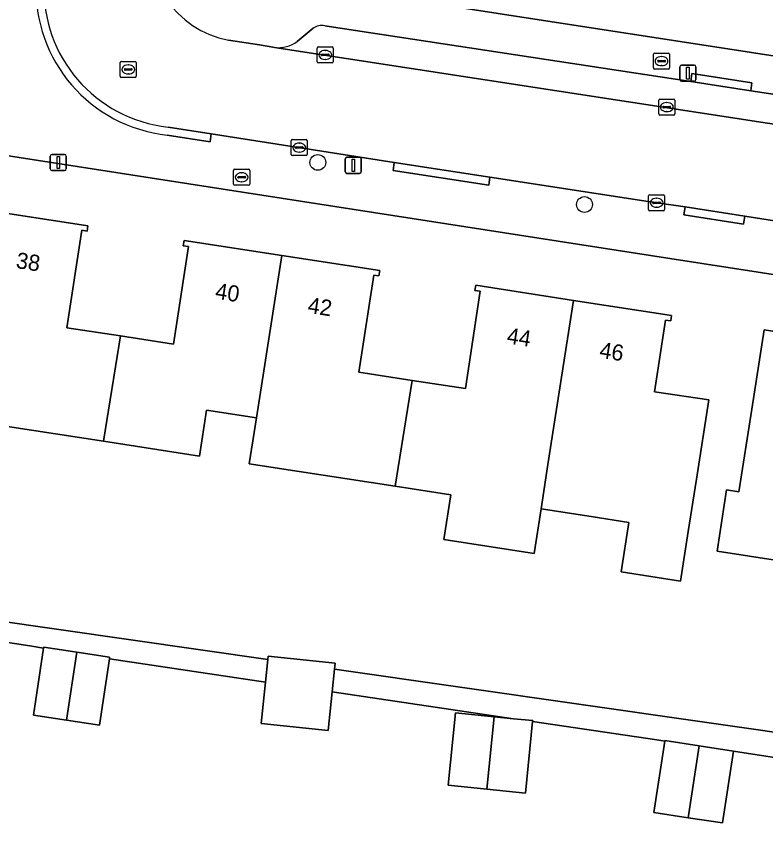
# Model space of a CAD drawing. Extents: x 161483 to 162250, y 379484 to 380833.
# Drawn here: x 161783.2 to 161829.9, y 380603.9 to 380654.4 of the extents above; entities that cross this region are included whole.
import ezdxf

# ---------------------------------------------------------------- set-up
doc = ezdxf.new("R2010")
doc.units = 0
for name, color, linetype in [('IMGEO_Boom', 7, 'Continuous'), ('IMGEO_Brandkraan', 7, 'Continuous'), ('IMGEO_Erf', 7, 'Continuous'), ('IMGEO_Kolk', 7, 'Continuous'), ('IMGEO_Lichtmast', 7, 'Continuous'), ('IMGEO_Pand', 7, 'Continuous'), ('IMGEO_Pand_nummerreeks', 7, 'Continuous'), ('IMGEO_Parkeervlak_open', 7, 'Continuous'), ('IMGEO_Rijbaan_lokaal_open', 7, 'Continuous'), ('IMGEO_Rioolput', 7, 'Continuous'), ('IMGEO_Voetpad_open', 7, 'Continuous')]:
    doc.layers.add(name, color=color, linetype=linetype)

msp = doc.modelspace()

# ---------------------------------------------------------------- linework, layer by layer
at = {"layer": 'IMGEO_Boom'}
for centre in [(161801.982, 380645.267), (161818.588, 380642.647)]:
    msp.add_circle(centre, 0.489, dxfattribs=at)
at = {"layer": 'IMGEO_Brandkraan'}
for p, q in [((161822.886, 380651.149), (161822.886, 380652.001)), ((161822.961, 380652.075), (161823.813, 380652.075)), ((161823.887, 380652.001), (161823.887, 380651.149)), ((161823.145, 380651.569), (161823.145, 380651.581)), ((161823.583, 380651.532), (161823.185, 380651.532)), ((161823.188, 380651.618), (161823.586, 380651.618)), ((161823.374, 380651.855), (161823.399, 380651.855)), ((161823.629, 380651.581), (161823.629, 380651.569)), ((161823.813, 380651.075), (161822.961, 380651.075)), ((161823.397, 380651.295), (161823.372, 380651.295)), ((161796.739, 380643.916), (161796.739, 380644.768)), ((161796.814, 380644.842), (161797.666, 380644.842)), ((161797.227, 380644.622), (161797.252, 380644.622)), ((161797.74, 380644.768), (161797.74, 380643.916)), ((161796.998, 380644.336), (161796.998, 380644.348)), ((161797.436, 380644.299), (161797.038, 380644.299)), ((161797.041, 380644.385), (161797.439, 380644.385)), ((161797.25, 380644.062), (161797.225, 380644.062)), ((161797.482, 380644.348), (161797.482, 380644.336)), ((161797.666, 380643.842), (161796.814, 380643.842))]:
    msp.add_line(p, q, dxfattribs=at)
for points in [[(161822.886, 380651.149), (161822.886, 380652.001)], [(161822.961, 380652.075), (161823.813, 380652.075)], [(161823.887, 380652.001), (161823.887, 380651.149)], [(161823.813, 380651.075), (161822.961, 380651.075)], [(161796.739, 380643.916), (161796.739, 380644.768)], [(161796.814, 380644.842), (161797.666, 380644.842)], [(161797.74, 380644.768), (161797.74, 380643.916)], [(161797.666, 380643.842), (161796.814, 380643.842)]]:
    msp.add_lwpolyline(points, dxfattribs=at)
for centre, radius, start, end in [((161822.963, 380651.999), 0.0765, 91.552, 178.448), ((161822.963, 380651.999), 0.0765, 91.552, 178.448), ((161823.811, 380651.999), 0.0765, 1.552, 88.448), ((161823.811, 380651.999), 0.0765, 1.552, 88.448), ((161823.185, 380651.578), 0.0403, 85.8775, 175.7526), ((161823.182, 380651.568), 0.0366, 178.938, 274.7102), ((161823.586, 380651.575), 0.043, 264.8664, 352.4533), ((161823.59, 380651.58), 0.0386, 1.7309, 96.639), ((161822.963, 380651.151), 0.0765, 181.552, 268.448), ((161822.963, 380651.151), 0.0765, 181.552, 268.448), ((161823.811, 380651.151), 0.0765, 271.552, 358.448), ((161823.811, 380651.151), 0.0765, 271.552, 358.448), ((161796.816, 380644.766), 0.0765, 91.552, 178.448), ((161796.816, 380644.766), 0.0765, 91.552, 178.448), ((161797.664, 380644.766), 0.0765, 1.552, 88.448), ((161797.664, 380644.766), 0.0765, 1.552, 88.448), ((161796.816, 380643.918), 0.0765, 181.552, 268.448), ((161796.816, 380643.918), 0.0765, 181.552, 268.448), ((161797.038, 380644.345), 0.0403, 85.8775, 175.7526), ((161797.035, 380644.335), 0.0366, 178.938, 274.7102), ((161797.439, 380644.342), 0.043, 264.8664, 352.4533), ((161797.443, 380644.347), 0.0386, 1.7309, 96.639), ((161797.664, 380643.918), 0.0765, 271.552, 358.448), ((161797.664, 380643.918), 0.0765, 271.552, 358.448)]:
    msp.add_arc(centre, radius, start, end, dxfattribs=at)
for centre, major_axis, ratio, start_param, end_param in [((161823.373, 380651.575), (-0.387, 0.002), 0.722429, 4.712389, 7.853982), ((161823.398, 380651.575), (-0.39, 0.002), 0.717154, 1.570796, 4.712389), ((161797.226, 380644.342), (-0.387, 0.002), 0.722429, 4.712389, 7.853982), ((161797.251, 380644.342), (-0.39, 0.002), 0.717154, 1.570796, 4.712389)]:
    msp.add_ellipse(centre, major_axis=major_axis, ratio=ratio, start_param=start_param, end_param=end_param, dxfattribs=at)
at = {"layer": 'IMGEO_Erf'}
for points in [[(161797.167, 380657.035), (161908.673, 380639.841), (161916.207, 380638.698), (161924.835, 380637.387), (161925.546, 380637.356)], [(161925.898, 380623.516), (161823.912, 380639.282), (161780.025, 380646.103), (161736.717, 380652.782), (161731.74, 380653.484)], [(161781.58, 380642.258), (161787.666, 380641.32), (161787.616, 380640.993), (161787.29, 380641.044), (161786.358, 380634.978), (161789.687, 380634.467), (161792.998, 380633.958), (161793.93, 380640.023), (161793.604, 380640.074), (161793.654, 380640.4), (161799.746, 380639.465), (161805.836, 380638.53), (161805.786, 380638.203), (161805.46, 380638.254), (161804.538, 380632.197), (161807.856, 380631.692), (161811.168, 380631.187), (161812.09, 380637.243), (161811.764, 380637.294), (161811.814, 380637.62), (161817.913, 380636.675), (161824.006, 380635.73), (161823.956, 380635.403), (161823.63, 380635.454), (161822.953, 380630.988), (161826.326, 380630.476), (161825.556, 380625.536), (161825.049, 380622.281), (161824.568, 380619.197), (161820.88, 380619.771), (161821.359, 380622.85), (161818.996, 380623.215), (161815.883, 380623.695), (161815.451, 380620.921), (161809.836, 380621.788), (161810.265, 380624.564), (161806.802, 380625.099), (161800.829, 380626.022), (161797.717, 380626.503), (161798.158, 380629.356), (161795.049, 380629.836), (161794.609, 380626.983), (161788.635, 380627.906), (161782.662, 380628.828)], [(161750.43, 380622.432), (161754.893, 380621.765), (161759.356, 380621.098), (161763.819, 380620.431), (161768.779, 380619.69), (161768.624, 380618.651), (161798.865, 380614.315), (161798.885, 380614.516), (161803.054, 380614.092), (161803.016, 380613.72), (161879.814, 380602.708)], [(161832.16, 380607.936), (161827.864, 380608.608), (161827.178, 380604.134), (161825.044, 380604.461), (161822.91, 380604.788), (161823.592, 380609.237), (161823.099, 380609.308), (161815.359, 380610.453), (161814.905, 380605.994), (161812.5, 380606.239), (161810.095, 380606.484), (161810.554, 380610.997), (161812.959, 380610.752), (161814.172, 380610.628), (161802.871, 380612.3), (161802.627, 380609.9), (161798.458, 380610.324), (161798.722, 380612.913), (161789, 380614.351), (161788.386, 380610.234), (161786.334, 380610.54), (161784.283, 380610.847), (161784.905, 380615.016), (161784.042, 380615.157), (161777.083, 380616.222)]]:
    msp.add_lwpolyline(points, dxfattribs=at)
msp.add_lwpolyline([(161830.564, 380618.414), (161830.878, 380620.439), (161826.847, 380621.064), (161827.438, 380624.873), (161828.206, 380624.754), (161829.004, 380629.9), (161829.77, 380634.84), (161835.7, 380633.93), (161835.178, 380630.68), (161838.733, 380630.109), (161837.972, 380625.168), (161836.784, 380617.449)], close=True, dxfattribs=at)
at = {"layer": 'IMGEO_Kolk'}
for p, q in [((161801.946, 380651.539), (161801.946, 380652.391)), ((161802.021, 380652.465), (161802.873, 380652.465)), ((161802.248, 380652.008), (161802.646, 380652.008)), ((161802.434, 380652.245), (161802.459, 380652.245)), ((161802.947, 380652.391), (161802.947, 380651.539)), ((161802.205, 380651.959), (161802.205, 380651.971)), ((161802.643, 380651.922), (161802.245, 380651.922)), ((161802.457, 380651.685), (161802.432, 380651.685)), ((161802.689, 380651.971), (161802.689, 380651.959)), ((161802.873, 380651.465), (161802.021, 380651.465)), ((161823.211, 380648.286), (161823.211, 380649.138)), ((161823.286, 380649.212), (161824.138, 380649.212)), ((161823.699, 380648.992), (161823.724, 380648.992)), ((161824.212, 380649.138), (161824.212, 380648.286)), ((161823.47, 380648.706), (161823.47, 380648.718)), ((161823.908, 380648.669), (161823.51, 380648.669)), ((161823.513, 380648.755), (161823.911, 380648.755)), ((161823.954, 380648.718), (161823.954, 380648.706)), ((161824.138, 380648.212), (161823.286, 380648.212)), ((161823.722, 380648.432), (161823.697, 380648.432)), ((161800.327, 380645.764), (161800.327, 380646.616)), ((161800.402, 380646.69), (161801.254, 380646.69)), ((161800.815, 380646.47), (161800.84, 380646.47)), ((161801.328, 380646.616), (161801.328, 380645.764)), ((161800.586, 380646.184), (161800.586, 380646.196)), ((161801.024, 380646.147), (161800.626, 380646.147)), ((161800.629, 380646.233), (161801.027, 380646.233)), ((161801.07, 380646.196), (161801.07, 380646.184)), ((161801.254, 380645.69), (161800.402, 380645.69)), ((161800.838, 380645.91), (161800.813, 380645.91)), ((161822.579, 380642.331), (161822.579, 380643.183)), ((161822.654, 380643.257), (161823.506, 380643.257)), ((161823.067, 380643.037), (161823.092, 380643.037)), ((161823.58, 380643.183), (161823.58, 380642.331)), ((161822.838, 380642.751), (161822.838, 380642.763)), ((161823.276, 380642.714), (161822.878, 380642.714)), ((161822.881, 380642.8), (161823.279, 380642.8)), ((161823.09, 380642.477), (161823.065, 380642.477)), ((161823.322, 380642.763), (161823.322, 380642.751)), ((161823.506, 380642.257), (161822.654, 380642.257))]:
    msp.add_line(p, q, dxfattribs=at)
for points in [[(161801.946, 380651.539), (161801.946, 380652.391)], [(161802.021, 380652.465), (161802.873, 380652.465)], [(161802.947, 380652.391), (161802.947, 380651.539)], [(161802.873, 380651.465), (161802.021, 380651.465)], [(161823.211, 380648.286), (161823.211, 380649.138)], [(161823.286, 380649.212), (161824.138, 380649.212)], [(161824.212, 380649.138), (161824.212, 380648.286)], [(161824.138, 380648.212), (161823.286, 380648.212)], [(161800.327, 380645.764), (161800.327, 380646.616)], [(161800.402, 380646.69), (161801.254, 380646.69)], [(161801.328, 380646.616), (161801.328, 380645.764)], [(161801.254, 380645.69), (161800.402, 380645.69)], [(161822.579, 380642.331), (161822.579, 380643.183)], [(161822.654, 380643.257), (161823.506, 380643.257)], [(161823.58, 380643.183), (161823.58, 380642.331)], [(161823.506, 380642.257), (161822.654, 380642.257)]]:
    msp.add_lwpolyline(points, dxfattribs=at)
for centre, radius, start, end in [((161802.023, 380652.389), 0.0765, 91.552, 178.448), ((161802.023, 380652.389), 0.0765, 91.552, 178.448), ((161802.245, 380651.968), 0.0403, 85.8775, 175.7526), ((161802.65, 380651.97), 0.0386, 1.7309, 96.639), ((161802.871, 380652.389), 0.0765, 1.552, 88.448), ((161802.871, 380652.389), 0.0765, 1.552, 88.448), ((161802.023, 380651.541), 0.0765, 181.552, 268.448), ((161802.023, 380651.541), 0.0765, 181.552, 268.448), ((161802.242, 380651.958), 0.0366, 178.938, 274.7102), ((161802.646, 380651.965), 0.043, 264.8664, 352.4533), ((161802.871, 380651.541), 0.0765, 271.552, 358.448), ((161802.871, 380651.541), 0.0765, 271.552, 358.448), ((161823.288, 380649.136), 0.0765, 91.552, 178.448), ((161823.288, 380649.136), 0.0765, 91.552, 178.448), ((161824.136, 380649.136), 0.0765, 1.552, 88.448), ((161824.136, 380649.136), 0.0765, 1.552, 88.448), ((161823.51, 380648.715), 0.0403, 85.8775, 175.7526), ((161823.507, 380648.705), 0.0366, 178.938, 274.7102), ((161823.911, 380648.712), 0.043, 264.8664, 352.4533), ((161823.915, 380648.717), 0.0386, 1.7309, 96.639), ((161823.288, 380648.288), 0.0765, 181.552, 268.448), ((161823.288, 380648.288), 0.0765, 181.552, 268.448), ((161824.136, 380648.288), 0.0765, 271.552, 358.448), ((161824.136, 380648.288), 0.0765, 271.552, 358.448), ((161800.404, 380646.614), 0.0765, 91.552, 178.448), ((161800.404, 380646.614), 0.0765, 91.552, 178.448), ((161801.252, 380646.614), 0.0765, 1.552, 88.448), ((161801.252, 380646.614), 0.0765, 1.552, 88.448), ((161800.626, 380646.193), 0.0403, 85.8775, 175.7526), ((161800.623, 380646.183), 0.0366, 178.938, 274.7102), ((161801.027, 380646.19), 0.043, 264.8664, 352.4533), ((161801.031, 380646.195), 0.0386, 1.7309, 96.639), ((161800.404, 380645.766), 0.0765, 181.552, 268.448), ((161800.404, 380645.766), 0.0765, 181.552, 268.448), ((161801.252, 380645.766), 0.0765, 271.552, 358.448), ((161801.252, 380645.766), 0.0765, 271.552, 358.448), ((161822.656, 380643.181), 0.0765, 91.552, 178.448), ((161822.656, 380643.181), 0.0765, 91.552, 178.448), ((161823.504, 380643.181), 0.0765, 1.552, 88.448), ((161823.504, 380643.181), 0.0765, 1.552, 88.448), ((161822.878, 380642.76), 0.0403, 85.8775, 175.7526), ((161822.875, 380642.75), 0.0366, 178.938, 274.7102), ((161823.279, 380642.757), 0.043, 264.8664, 352.4533), ((161823.283, 380642.762), 0.0386, 1.7309, 96.639), ((161822.656, 380642.333), 0.0765, 181.552, 268.448), ((161822.656, 380642.333), 0.0765, 181.552, 268.448), ((161823.504, 380642.333), 0.0765, 271.552, 358.448), ((161823.504, 380642.333), 0.0765, 271.552, 358.448)]:
    msp.add_arc(centre, radius, start, end, dxfattribs=at)
for centre, major_axis, ratio, start_param, end_param in [((161802.433, 380651.965), (-0.387, 0.002), 0.722429, 4.712389, 7.853982), ((161802.458, 380651.965), (-0.39, 0.002), 0.717154, 1.570796, 4.712389), ((161823.698, 380648.712), (-0.387, 0.002), 0.722429, 4.712389, 7.853982), ((161823.723, 380648.712), (-0.39, 0.002), 0.717154, 1.570796, 4.712389), ((161800.814, 380646.19), (-0.387, 0.002), 0.722429, 4.712389, 7.853982), ((161800.839, 380646.19), (-0.39, 0.002), 0.717154, 1.570796, 4.712389), ((161823.066, 380642.757), (-0.387, 0.002), 0.722429, 4.712389, 7.853982), ((161823.091, 380642.757), (-0.39, 0.002), 0.717154, 1.570796, 4.712389)]:
    msp.add_ellipse(centre, major_axis=major_axis, ratio=ratio, start_param=start_param, end_param=end_param, dxfattribs=at)
at = {"layer": 'IMGEO_Lichtmast'}
for p, q in [((161824.53, 380650.429), (161824.53, 380651.229)), ((161824.53, 380651.229), (161824.53, 380650.429)), ((161824.63, 380651.329), (161825.42, 380651.329)), ((161825.42, 380651.329), (161824.63, 380651.329)), ((161825.52, 380651.229), (161825.52, 380650.429)), ((161825.52, 380650.429), (161825.52, 380651.229)), ((161825.42, 380650.329), (161824.63, 380650.329)), ((161824.63, 380650.329), (161825.42, 380650.329)), ((161785.323, 380644.867), (161785.323, 380645.667)), ((161785.323, 380645.667), (161785.323, 380644.867)), ((161785.423, 380645.767), (161786.213, 380645.767)), ((161786.213, 380645.767), (161785.423, 380645.767)), ((161786.313, 380645.667), (161786.313, 380644.867)), ((161786.313, 380644.867), (161786.313, 380645.667)), ((161803.694, 380644.688), (161803.694, 380645.488)), ((161803.694, 380645.488), (161803.694, 380644.688)), ((161803.794, 380645.588), (161804.584, 380645.588)), ((161804.584, 380645.588), (161803.794, 380645.588)), ((161804.684, 380645.488), (161804.684, 380644.688)), ((161804.684, 380644.688), (161804.684, 380645.488)), ((161786.213, 380644.767), (161785.423, 380644.767)), ((161785.423, 380644.767), (161786.213, 380644.767)), ((161804.584, 380644.588), (161803.794, 380644.588)), ((161803.794, 380644.588), (161804.584, 380644.588))]:
    msp.add_line(p, q, dxfattribs=at)
for points in [[(161824.95, 380651.204), (161825.1, 380651.204), (161825.1, 380650.454), (161824.95, 380650.454), (161824.95, 380651.204)], [(161785.743, 380645.642), (161785.893, 380645.642), (161785.893, 380644.892), (161785.743, 380644.892), (161785.743, 380645.642)], [(161804.114, 380645.463), (161804.264, 380645.463), (161804.264, 380644.713), (161804.114, 380644.713), (161804.114, 380645.463)]]:
    msp.add_lwpolyline(points, dxfattribs=at)
for centre, start, end in [((161824.63, 380651.229), 90, 180), ((161824.63, 380651.229), 90, 180), ((161825.42, 380651.229), 0, 90), ((161825.42, 380651.229), 360, 90), ((161824.63, 380650.429), 180, 270), ((161824.63, 380650.429), 180, 270), ((161825.42, 380650.429), 270, 0), ((161825.42, 380650.429), 270, 0), ((161785.423, 380645.667), 90, 180), ((161785.423, 380645.667), 90, 180), ((161786.213, 380645.667), 0, 90), ((161786.213, 380645.667), 360, 90), ((161803.794, 380645.488), 90, 180), ((161803.794, 380645.488), 90, 180), ((161804.584, 380645.488), 0, 90), ((161804.584, 380645.488), 360, 90), ((161785.423, 380644.867), 180, 270), ((161785.423, 380644.867), 180, 270), ((161786.213, 380644.867), 270, 0), ((161786.213, 380644.867), 270, 0), ((161803.794, 380644.688), 180, 270), ((161803.794, 380644.688), 180, 270), ((161804.584, 380644.688), 270, 0), ((161804.584, 380644.688), 270, 0)]:
    msp.add_arc(centre, 0.1, start, end, dxfattribs=at)
at = {"layer": 'IMGEO_Pand'}
for points in [[(161781.58, 380642.258), (161779.99, 380632.163), (161779.541, 380629.311), (161779.401, 380628.422), (161782.525, 380627.941), (161782.662, 380628.828), (161788.635, 380627.906), (161789.687, 380634.467), (161786.358, 380634.978), (161787.29, 380641.044), (161787.616, 380640.993), (161787.666, 380641.32)], [(161789.687, 380634.467), (161788.635, 380627.906), (161794.609, 380626.983), (161795.049, 380629.836), (161798.158, 380629.356), (161799.746, 380639.465), (161793.654, 380640.4), (161793.604, 380640.074), (161793.93, 380640.023), (161792.998, 380633.958)], [(161799.746, 380639.465), (161798.158, 380629.356), (161797.717, 380626.503), (161800.829, 380626.022), (161806.802, 380625.099), (161807.856, 380631.692), (161804.538, 380632.197), (161805.46, 380638.254), (161805.786, 380638.203), (161805.836, 380638.53)], [(161817.913, 380636.675), (161811.814, 380637.62), (161811.764, 380637.294), (161812.09, 380637.243), (161811.168, 380631.187), (161807.856, 380631.692), (161806.802, 380625.099), (161810.265, 380624.564), (161809.836, 380621.788), (161815.451, 380620.921), (161815.883, 380623.695), (161816.314, 380626.46)], [(161817.913, 380636.675), (161816.314, 380626.46), (161815.883, 380623.695), (161818.996, 380623.215), (161821.359, 380622.85), (161820.88, 380619.771), (161824.568, 380619.197), (161825.049, 380622.281), (161825.556, 380625.536), (161826.326, 380630.476), (161822.953, 380630.988), (161823.63, 380635.454), (161823.956, 380635.403), (161824.006, 380635.73)], [(161830.878, 380620.439), (161830.564, 380618.414), (161836.784, 380617.449), (161837.972, 380625.168), (161838.733, 380630.109), (161835.178, 380630.68), (161835.7, 380633.93), (161829.77, 380634.84), (161829.004, 380629.9), (161828.206, 380624.754), (161827.438, 380624.873), (161826.847, 380621.064)], [(161786.965, 380614.771), (161784.914, 380615.077), (161784.905, 380615.016), (161784.283, 380610.847), (161786.334, 380610.54)], [(161789, 380614.351), (161789.017, 380614.464), (161786.965, 380614.771), (161786.334, 380610.54), (161788.386, 380610.234)], [(161803.016, 380613.72), (161803.054, 380614.092), (161798.885, 380614.516), (161798.865, 380614.315), (161798.722, 380612.913), (161798.458, 380610.324), (161802.627, 380609.9), (161802.871, 380612.3)], [(161812.959, 380610.752), (161810.554, 380610.997), (161810.095, 380606.484), (161812.5, 380606.239)], [(161815.359, 380610.453), (161815.364, 380610.507), (161814.172, 380610.628), (161812.959, 380610.752), (161812.5, 380606.239), (161814.905, 380605.994)], [(161825.73, 380608.935), (161823.596, 380609.262), (161823.592, 380609.237), (161822.91, 380604.788), (161825.044, 380604.461)], [(161826.133, 380608.873), (161825.73, 380608.935), (161825.044, 380604.461), (161827.178, 380604.134), (161827.864, 380608.608)]]:
    msp.add_lwpolyline(points, close=True, dxfattribs=at)
at = {"layer": 'IMGEO_Parkeervlak_open'}
for points in [[(161801.694, 380653.623), (161800.698, 380652.804)], [(161918.986, 380635.854), (161896.349, 380639.345), (161892.581, 380639.926), (161887.663, 380640.685), (161883.909, 380641.264), (161878.553, 380642.09), (161874.831, 380642.664), (161869.575, 380643.474), (161865.816, 380644.054), (161855.606, 380645.629), (161851.871, 380646.205), (161846.947, 380646.964), (161843.17, 380647.547), (161837.894, 380648.36), (161834.174, 380648.934), (161828.937, 380649.734), (161825.202, 380650.315), (161802.414, 380653.775)], [(161799.277, 380652.426), (161896.119, 380637.555), (161921.635, 380633.64)]]:
    msp.add_lwpolyline(points, dxfattribs=at)
for centre, radius, start, end in [((161802.217, 380652.929), 0.869, 76.8563, 126.9852), ((161799.523, 380654.363), 1.952, 262.7759, 307.0167)]:
    msp.add_arc(centre, radius, start, end, dxfattribs=at)
at = {"layer": 'IMGEO_Rijbaan_lokaal_open'}
for points in [[(161923.89, 380633.266), (161921.92, 380633.58), (161921.635, 380633.64), (161896.119, 380637.555), (161799.277, 380652.426), (161799.176, 380652.442), (161798.35, 380652.6), (161796.411, 380652.873)], [(161792.657, 380647.471), (161795.339, 380647.057), (161806.744, 380645.255), (161812.698, 380644.355), (161823.086, 380642.759), (161824.853, 380642.493), (161828.567, 380641.917), (161836.508, 380640.681)]]:
    msp.add_lwpolyline(points, dxfattribs=at)
for centre, radius, start, end in [((161797.596, 380658.89), 6.132, 169.8728, 258.8607), ((161793.574, 380656.07), 8.648, 177.6361, 263.9154)]:
    msp.add_arc(centre, radius, start, end, dxfattribs=at)
at = {"layer": 'IMGEO_Rioolput'}
for p, q in [((161789.677, 380650.632), (161789.677, 380651.484)), ((161789.752, 380651.558), (161790.604, 380651.558)), ((161790.678, 380651.484), (161790.678, 380650.632)), ((161789.936, 380651.052), (161789.936, 380651.064)), ((161790.374, 380651.015), (161789.976, 380651.015)), ((161789.979, 380651.101), (161790.377, 380651.101)), ((161790.165, 380651.338), (161790.19, 380651.338)), ((161790.42, 380651.064), (161790.42, 380651.052)), ((161790.604, 380650.558), (161789.752, 380650.558)), ((161790.188, 380650.778), (161790.163, 380650.778))]:
    msp.add_line(p, q, dxfattribs=at)
for points in [[(161789.677, 380650.632), (161789.677, 380651.484)], [(161789.752, 380651.558), (161790.604, 380651.558)], [(161790.678, 380651.484), (161790.678, 380650.632)], [(161790.604, 380650.558), (161789.752, 380650.558)]]:
    msp.add_lwpolyline(points, dxfattribs=at)
for centre, radius, start, end in [((161789.754, 380651.482), 0.0765, 91.552, 178.448), ((161789.754, 380651.482), 0.0765, 91.552, 178.448), ((161790.602, 380651.482), 0.0765, 1.552, 88.448), ((161790.602, 380651.482), 0.0765, 1.552, 88.448), ((161789.976, 380651.061), 0.0403, 85.8775, 175.7526), ((161789.973, 380651.051), 0.0366, 178.938, 274.7102), ((161790.377, 380651.058), 0.043, 264.8664, 352.4533), ((161790.381, 380651.063), 0.0386, 1.7309, 96.639), ((161789.754, 380650.634), 0.0765, 181.552, 268.448), ((161789.754, 380650.634), 0.0765, 181.552, 268.448), ((161790.602, 380650.634), 0.0765, 271.552, 358.448), ((161790.602, 380650.634), 0.0765, 271.552, 358.448)]:
    msp.add_arc(centre, radius, start, end, dxfattribs=at)
for centre, major_axis, ratio, start_param, end_param in [((161790.164, 380651.058), (-0.387, 0.002), 0.722429, 4.712389, 7.853982), ((161790.189, 380651.058), (-0.39, 0.002), 0.717154, 1.570796, 4.712389)]:
    msp.add_ellipse(centre, major_axis=major_axis, ratio=ratio, start_param=start_param, end_param=end_param, dxfattribs=at)
at = {"layer": 'IMGEO_Voetpad_open'}
for points in [[(161807.605, 380805.299), (161802.298, 380806.133), (161797.296, 380773.35), (161796.862, 380770.298), (161796.426, 380767.228), (161798.606, 380766.939), (161795.986, 380750), (161793.024, 380730.851), (161790.225, 380712.603), (161787.978, 380697.958), (161781.385, 380654.948), (161780.025, 380646.103), (161823.912, 380639.282), (161925.898, 380623.516)], [(161925.546, 380637.356), (161924.835, 380637.387), (161916.207, 380638.698), (161908.673, 380639.841), (161797.167, 380657.035)], [(161800.698, 380652.804), (161801.694, 380653.623)], [(161802.414, 380653.775), (161825.202, 380650.315), (161825.278, 380650.809), (161829.013, 380650.228), (161828.937, 380649.734), (161834.174, 380648.934)], [(161796.411, 380652.873), (161798.35, 380652.6), (161799.176, 380652.442), (161799.277, 380652.426)], [(161792.604, 380646.974), (161795.27, 380646.555), (161795.339, 380647.057), (161792.657, 380647.471)], [(161836.508, 380640.681), (161828.567, 380641.917), (161828.491, 380641.423), (161824.777, 380641.999), (161824.853, 380642.493), (161823.086, 380642.759), (161812.698, 380644.355), (161812.624, 380643.861), (161806.67, 380644.761), (161806.744, 380645.255), (161795.339, 380647.057), (161795.27, 380646.555), (161792.604, 380646.974)], [(161879.814, 380602.708), (161803.016, 380613.72), (161802.871, 380612.3), (161814.172, 380610.628), (161815.364, 380610.507), (161815.359, 380610.453), (161823.099, 380609.308), (161823.592, 380609.237), (161823.596, 380609.262), (161825.73, 380608.935), (161826.133, 380608.873), (161827.864, 380608.608), (161832.16, 380607.936), (161834.286, 380607.61), (161842.393, 380606.367), (161842.385, 380606.316), (161845.162, 380605.856), (161846.266, 380603.381)]]:
    msp.add_lwpolyline(points, dxfattribs=at)
for points in [[(161825.202, 380650.315), (161828.937, 380649.734), (161829.013, 380650.228), (161825.278, 380650.809)], [(161806.744, 380645.255), (161806.67, 380644.761), (161812.624, 380643.861), (161812.698, 380644.355)], [(161824.853, 380642.493), (161824.777, 380641.999), (161828.491, 380641.423), (161828.567, 380641.917)], [(161768.624, 380618.651), (161768.779, 380619.69), (161763.819, 380620.431), (161762.965, 380614.72), (161762.888, 380614.224), (161764.751, 380613.935), (161765.359, 380618.012), (161768.486, 380617.565), (161772.686, 380616.922), (161777.083, 380616.222), (161784.042, 380615.157), (161784.905, 380615.016), (161784.914, 380615.077), (161786.965, 380614.771), (161789.017, 380614.464), (161789, 380614.351), (161798.722, 380612.913), (161798.865, 380614.315)]]:
    msp.add_lwpolyline(points, close=True, dxfattribs=at)
for centre, radius, start, end in [((161797.596, 380658.89), 6.132, 169.8728, 258.8607), ((161793.574, 380656.071), 9.149, 177.6393, 263.914), ((161793.574, 380656.071), 9.149, 177.6393, 263.914), ((161793.574, 380656.07), 8.648, 177.6361, 263.9154), ((161802.217, 380652.929), 0.869, 76.8563, 126.9852), ((161799.523, 380654.363), 1.952, 262.7759, 307.0167)]:
    msp.add_arc(centre, radius, start, end, dxfattribs=at)

# ---------------------------------------------------------------- texts
at = {"layer": 'IMGEO_Pand_nummerreeks'}
for s, rotation, p in [('38', 351.2337, (161783.141, 380638.699)), ('40', 351.2729, (161795.551, 380636.79)), ('42', 351.2729, (161801.309, 380635.906)), ('44', 351.1879, (161813.706, 380634.008)), ('46', 351.1882, (161819.475, 380633.113))]:
    msp.add_text(s, height=1, rotation=rotation, dxfattribs=at).set_placement(p)

doc.saveas('drawing.dxf')
